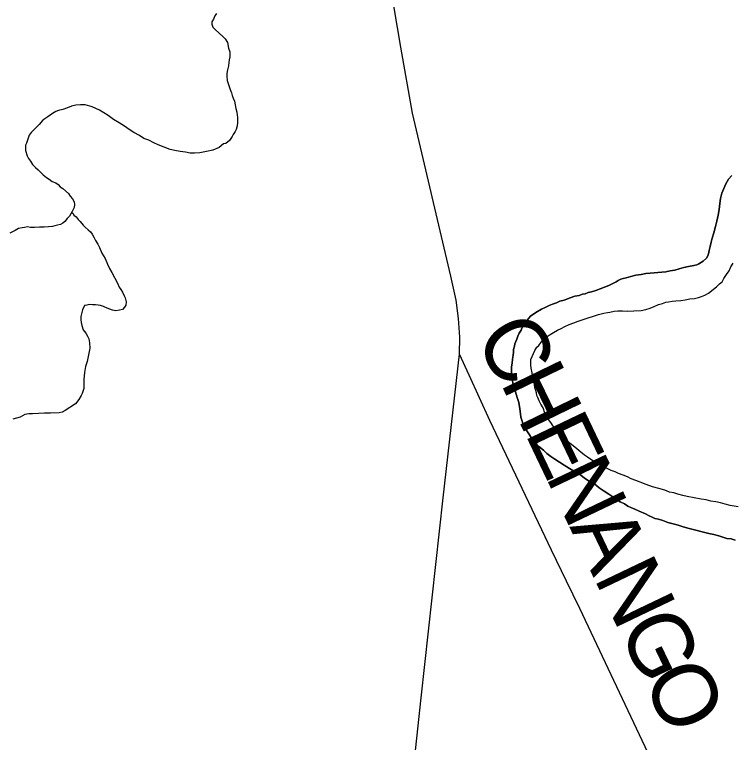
# Model space of a CAD drawing. Extents: x 0 to 34, y 0 to 22.
# Drawn here: x 4.849 to 5.486, y 16.477 to 17.124 of the extents above; entities that cross this region are included whole.
import ezdxf

# ---------------------------------------------------------------- set-up
doc = ezdxf.new("R2010")
doc.units = 0
for name, color, linetype in [('GM_X_Major_River', 7, 'Continuous'), ('GM_X_Minor_River', 7, 'Continuous'), ('GM_X_State_Route', 7, 'Continuous'), ('GM_X_Township_Road', 7, 'Continuous'), ('GM_X_Township_Road_Text', 7, 'Continuous')]:
    doc.layers.add(name, color=color, linetype=linetype)

msp = doc.modelspace()

# ---------------------------------------------------------------- linework, layer by layer
at = {"layer": 'GM_X_Major_River'}
for points in [[(5.48664, 16.98054), (5.48356, 16.97716), (5.48123, 16.973), (5.47928, 16.96884), (5.47771, 16.96468), (5.47652, 16.96013), (5.4757, 16.95558), (5.47526, 16.95027), (5.47444, 16.94533), (5.47323, 16.94003), (5.47203, 16.9351), (5.47044, 16.92941), (5.46887, 16.92487), (5.46806, 16.92108), (5.46726, 16.91729), (5.46646, 16.91388), (5.46566, 16.91084), (5.46526, 16.90895), (5.46409, 16.90706), (5.46102, 16.90444), (5.45719, 16.90182), (5.45528, 16.90109), (5.45261, 16.90036), (5.44804, 16.89965), (5.44384, 16.89856), (5.43965, 16.89747), (5.43583, 16.89637), (5.43164, 16.89566), (5.42783, 16.89495), (5.42441, 16.89461), (5.41375, 16.89359), (5.40995, 16.89326), (5.40576, 16.89255), (5.40119, 16.89184), (5.39661, 16.89076), (5.39242, 16.88967), (5.38975, 16.88894), (5.38784, 16.8882), (5.38554, 16.88709), (5.38363, 16.88597), (5.38057, 16.88448), (5.37713, 16.88262), (5.37331, 16.88115), (5.36949, 16.87967), (5.36567, 16.8782), (5.36186, 16.8771), (5.35881, 16.87638), (5.35613, 16.87527), (5.35385, 16.87492), (5.35079, 16.87381), (5.34698, 16.8731), (5.34279, 16.87163), (5.33744, 16.86979), (5.33363, 16.8687), (5.33057, 16.86721), (5.32713, 16.86611), (5.32408, 16.86501), (5.32102, 16.86352), (5.3172, 16.86167), (5.31222, 16.85869), (5.30761, 16.85532), (5.30453, 16.85194), (5.3026, 16.84892), (5.30028, 16.84628), (5.2991, 16.84287), (5.29755, 16.84023), (5.29638, 16.83759), (5.29521, 16.83494), (5.29364, 16.83078), (5.29323, 16.82888), (5.29244, 16.82585), (5.29241, 16.82357), (5.292, 16.82091), (5.29157, 16.81712), (5.29115, 16.8137), (5.29073, 16.81028), (5.29068, 16.80648), (5.29064, 16.80344), (5.2917, 16.79621), (5.29279, 16.79239), (5.29426, 16.78819), (5.29572, 16.78323), (5.29719, 16.77866), (5.29788, 16.77295), (5.29859, 16.76876), (5.29893, 16.76571), (5.29966, 16.76304), (5.30077, 16.76037), (5.30225, 16.75693), (5.30411, 16.75349), (5.30673, 16.75003)], [(5.30673, 16.75003), (5.30411, 16.75349), (5.30225, 16.75693), (5.30077, 16.76037), (5.29966, 16.76304), (5.29893, 16.76571), (5.29859, 16.76876), (5.29788, 16.77295), (5.29719, 16.77866), (5.29572, 16.78323), (5.29426, 16.78819), (5.29279, 16.79239), (5.2917, 16.79621), (5.29064, 16.80344), (5.29068, 16.80648), (5.29073, 16.81028), (5.29115, 16.8137), (5.29157, 16.81712), (5.292, 16.82091), (5.29241, 16.82357), (5.29244, 16.82585), (5.29323, 16.82888), (5.29364, 16.83078), (5.29521, 16.83494), (5.29638, 16.83759), (5.29755, 16.84023), (5.2991, 16.84287), (5.30028, 16.84628), (5.3026, 16.84892), (5.30453, 16.85194), (5.30761, 16.85532), (5.31222, 16.85869), (5.3172, 16.86167), (5.32102, 16.86352), (5.32408, 16.86501), (5.32713, 16.86611), (5.33057, 16.86721), (5.33363, 16.8687), (5.33744, 16.86979), (5.34279, 16.87163), (5.34698, 16.8731), (5.35079, 16.87381), (5.35385, 16.87492), (5.35613, 16.87527), (5.35881, 16.87638), (5.36186, 16.8771), (5.36567, 16.8782), (5.36949, 16.87967), (5.37331, 16.88115), (5.37713, 16.88262), (5.38057, 16.88448), (5.38363, 16.88597), (5.38554, 16.88709), (5.38784, 16.8882), (5.38975, 16.88894), (5.39242, 16.88967), (5.39661, 16.89076), (5.40119, 16.89184), (5.40576, 16.89255), (5.40995, 16.89326), (5.41375, 16.89359), (5.42441, 16.89461), (5.42783, 16.89495), (5.43164, 16.89566), (5.43583, 16.89637), (5.43965, 16.89747), (5.44384, 16.89856), (5.44804, 16.89965), (5.45261, 16.90036), (5.45528, 16.90109), (5.45719, 16.90182), (5.46102, 16.90444), (5.46409, 16.90706), (5.46526, 16.90895), (5.46566, 16.91084), (5.46646, 16.91388), (5.46726, 16.91729), (5.46806, 16.92108), (5.46887, 16.92487), (5.47044, 16.92941), (5.47203, 16.9351), (5.47323, 16.94003), (5.47444, 16.94533), (5.47526, 16.95027), (5.4757, 16.95558), (5.47652, 16.96013), (5.47771, 16.96468), (5.47928, 16.96884), (5.48123, 16.973), (5.48356, 16.97716), (5.48664, 16.98054)], [(5.4214, 16.86575), (5.42484, 16.86685), (5.42789, 16.86796), (5.43018, 16.86831), (5.4336, 16.86865), (5.43665, 16.86899), (5.44121, 16.86932), (5.44502, 16.87004), (5.44921, 16.87075), (5.4534, 16.87108), (5.45683, 16.87218), (5.4595, 16.87291), (5.46256, 16.87401), (5.46562, 16.87587), (5.47291, 16.88149), (5.4756, 16.88412), (5.4779, 16.88599), (5.47946, 16.88901), (5.48178, 16.89241), (5.48411, 16.8958), (5.48567, 16.8992), (5.48761, 16.9026)], [(5.4214, 16.86575), (5.42484, 16.86685), (5.42789, 16.86796), (5.43018, 16.86831), (5.4336, 16.86865), (5.43665, 16.86899), (5.44121, 16.86932), (5.44502, 16.87004), (5.44921, 16.87075), (5.4534, 16.87108), (5.45683, 16.87218), (5.4595, 16.87291), (5.46256, 16.87401), (5.46562, 16.87587), (5.47291, 16.88149), (5.4756, 16.88412), (5.4779, 16.88599), (5.47946, 16.88901), (5.48178, 16.89241), (5.48411, 16.8958), (5.48567, 16.8992), (5.48761, 16.9026)], [(5.49222, 16.68587), (5.48502, 16.6871), (5.48047, 16.68829), (5.4763, 16.68948), (5.47213, 16.69029), (5.46796, 16.6911), (5.46379, 16.69229), (5.45924, 16.69273), (5.44672, 16.69516), (5.44293, 16.69596), (5.43838, 16.69716), (5.43497, 16.69834), (5.43118, 16.69914), (5.42702, 16.70071), (5.42172, 16.7023), (5.41604, 16.70388), (5.41036, 16.70585), (5.40506, 16.70781), (5.40127, 16.70938), (5.39711, 16.71095), (5.39371, 16.71251), (5.38993, 16.71408), (5.38576, 16.71565), (5.38274, 16.7172), (5.37933, 16.71838), (5.37518, 16.72033), (5.37102, 16.72228), (5.36724, 16.72423), (5.36422, 16.72616), (5.36121, 16.7281), (5.35819, 16.73004), (5.35555, 16.73197), (5.35216, 16.73467), (5.34689, 16.73891), (5.34275, 16.74238), (5.33899, 16.74585), (5.33561, 16.74893), (5.3326, 16.75201), (5.32998, 16.75508), (5.32773, 16.75777), (5.32549, 16.76084), (5.32362, 16.76352), (5.32213, 16.76619), (5.32027, 16.76926), (5.3188, 16.77384), (5.31656, 16.77729), (5.31508, 16.78034), (5.31397, 16.78302), (5.31323, 16.78493), (5.31288, 16.78721), (5.31214, 16.7895), (5.31141, 16.79179), (5.31107, 16.79484), (5.31035, 16.79789), (5.30963, 16.80132), (5.30891, 16.80513), (5.3082, 16.80932), (5.30785, 16.81198), (5.30791, 16.81692), (5.30909, 16.81957), (5.31026, 16.82222), (5.31143, 16.82486), (5.31299, 16.82789), (5.31491, 16.82938), (5.31684, 16.8324), (5.31877, 16.83428), (5.32146, 16.83691), (5.32491, 16.83915), (5.32797, 16.84101), (5.33141, 16.84287), (5.33485, 16.84435), (5.33792, 16.84622), (5.34174, 16.84807), (5.34594, 16.84954), (5.34976, 16.85102), (5.35357, 16.85211), (5.35892, 16.85395), (5.3635, 16.85542), (5.36808, 16.85688), (5.37265, 16.85797), (5.37608, 16.85869), (5.37799, 16.85905), (5.3818, 16.85976), (5.38522, 16.8601), (5.3894, 16.86005), (5.39396, 16.86), (5.39929, 16.86031), (5.40575, 16.86062), (5.40994, 16.86133), (5.41376, 16.86242), (5.41758, 16.8639), (5.4214, 16.86575)], [(5.49222, 16.68587), (5.48502, 16.6871), (5.48047, 16.68829), (5.4763, 16.68948), (5.47213, 16.69029), (5.46796, 16.6911), (5.46379, 16.69229), (5.45924, 16.69273), (5.44672, 16.69516), (5.44293, 16.69596), (5.43838, 16.69716), (5.43497, 16.69834), (5.43118, 16.69914), (5.42702, 16.70071), (5.42172, 16.7023), (5.41604, 16.70388), (5.41036, 16.70585), (5.40506, 16.70781), (5.40127, 16.70938), (5.39711, 16.71095), (5.39371, 16.71251), (5.38993, 16.71408), (5.38576, 16.71565), (5.38274, 16.7172), (5.37933, 16.71838), (5.37518, 16.72033), (5.37102, 16.72228), (5.36724, 16.72423), (5.36422, 16.72616), (5.36121, 16.7281), (5.35819, 16.73004), (5.35555, 16.73197), (5.35216, 16.73467), (5.34689, 16.73891), (5.34275, 16.74238), (5.33899, 16.74585), (5.33561, 16.74893), (5.3326, 16.75201), (5.32998, 16.75508), (5.32773, 16.75777), (5.32549, 16.76084), (5.32362, 16.76352), (5.32213, 16.76619), (5.32027, 16.76926), (5.3188, 16.77384), (5.31656, 16.77729), (5.31508, 16.78034), (5.31397, 16.78302), (5.31323, 16.78493), (5.31288, 16.78721), (5.31214, 16.7895), (5.31141, 16.79179), (5.31107, 16.79484), (5.31035, 16.79789), (5.30963, 16.80132), (5.30891, 16.80513), (5.3082, 16.80932), (5.30785, 16.81198), (5.30791, 16.81692), (5.30909, 16.81957), (5.31026, 16.82222), (5.31143, 16.82486), (5.31299, 16.82789), (5.31491, 16.82938), (5.31684, 16.8324), (5.31877, 16.83428), (5.32146, 16.83691), (5.32491, 16.83915), (5.32797, 16.84101), (5.33141, 16.84287), (5.33485, 16.84435), (5.33792, 16.84622), (5.34174, 16.84807), (5.34594, 16.84954), (5.34976, 16.85102), (5.35357, 16.85211), (5.35892, 16.85395), (5.3635, 16.85542), (5.36808, 16.85688), (5.37265, 16.85797), (5.37608, 16.85869), (5.37799, 16.85905), (5.3818, 16.85976), (5.38522, 16.8601), (5.3894, 16.86005), (5.39396, 16.86), (5.39929, 16.86031), (5.40575, 16.86062), (5.40994, 16.86133), (5.41376, 16.86242), (5.41758, 16.8639), (5.4214, 16.86575)], [(5.30673, 16.75003), (5.30897, 16.7462), (5.31159, 16.74313), (5.31497, 16.73967), (5.31911, 16.7362), (5.32212, 16.73351), (5.3255, 16.7308), (5.32928, 16.72848), (5.33343, 16.72577), (5.33758, 16.72306), (5.3421, 16.71996), (5.34663, 16.71725), (5.35116, 16.71491), (5.35531, 16.71182), (5.35908, 16.70912), (5.36436, 16.70639), (5.3685, 16.70292), (5.37303, 16.69983), (5.37718, 16.69712), (5.38057, 16.6948), (5.38397, 16.69248), (5.38736, 16.69054), (5.39114, 16.68859), (5.39416, 16.68666), (5.3968, 16.68548), (5.40021, 16.68392), (5.40399, 16.68198), (5.40966, 16.67963), (5.41306, 16.67807), (5.41571, 16.6769), (5.41798, 16.67573), (5.42139, 16.67493), (5.42517, 16.67374), (5.42972, 16.67217), (5.43426, 16.67097), (5.43881, 16.66978), (5.44336, 16.66821), (5.44866, 16.66662), (5.46609, 16.66223), (5.47064, 16.66142), (5.47481, 16.66023), (5.4786, 16.65905), (5.482, 16.65786), (5.4858, 16.65744), (5.48959, 16.65625)], [(5.48959, 16.65625), (5.4858, 16.65744), (5.482, 16.65786), (5.4786, 16.65905), (5.47481, 16.66023), (5.47064, 16.66142), (5.46609, 16.66223), (5.44866, 16.66662), (5.44336, 16.66821), (5.43881, 16.66978), (5.43426, 16.67097), (5.42972, 16.67217), (5.42517, 16.67374), (5.42139, 16.67493), (5.41798, 16.67573), (5.41571, 16.6769), (5.41306, 16.67807), (5.40966, 16.67963), (5.40399, 16.68198), (5.40021, 16.68392), (5.3968, 16.68548), (5.39416, 16.68666), (5.39114, 16.68859), (5.38736, 16.69054), (5.38397, 16.69248), (5.38057, 16.6948), (5.37718, 16.69712), (5.37303, 16.69983), (5.3685, 16.70292), (5.36436, 16.70639), (5.35908, 16.70912), (5.35531, 16.71182), (5.35116, 16.71491), (5.34663, 16.71725), (5.3421, 16.71996), (5.33758, 16.72306), (5.33343, 16.72577), (5.32928, 16.72848), (5.3255, 16.7308), (5.32212, 16.73351), (5.31911, 16.7362), (5.31497, 16.73967), (5.31159, 16.74313), (5.30897, 16.7462), (5.30673, 16.75003)]]:
    msp.add_lwpolyline(points, dxfattribs=at)
at = {"layer": 'GM_X_Minor_River'}
for points in [[(5.02841, 17.12434), (5.02687, 17.12246), (5.02569, 17.11943), (5.02414, 17.11717), (5.02411, 17.11489), (5.02522, 17.11221), (5.0271, 17.11029), (5.03424, 17.10375), (5.03612, 17.10182), (5.03798, 17.09876), (5.03907, 17.0938), (5.04016, 17.09037), (5.04014, 17.08847), (5.04011, 17.08581), (5.0397, 17.08315), (5.03929, 17.08088), (5.03887, 17.07784), (5.03807, 17.07443), (5.03765, 17.07101), (5.03762, 17.06835), (5.03796, 17.06493), (5.03906, 17.06149), (5.04052, 17.05691), (5.04163, 17.05386), (5.04236, 17.05157), (5.04309, 17.04928), (5.0442, 17.04661), (5.04492, 17.04318), (5.04564, 17.04013), (5.04636, 17.0367), (5.04671, 17.03441), (5.04707, 17.03213), (5.04704, 17.02985), (5.04701, 17.02719), (5.0466, 17.02453), (5.0458, 17.0215), (5.04502, 17.01961), (5.04308, 17.01697), (5.0423, 17.01508), (5.03998, 17.01169), (5.03653, 17.00906), (5.03462, 17.00871), (5.03078, 17.00533), (5.02505, 17.00312), (5.01933, 17.00167), (5.01362, 17.00059), (5.00867, 17.00027), (5.00487, 17.00032), (5.0007, 17.00113), (4.99614, 17.00194), (4.99121, 17.00276), (4.98704, 17.00357), (4.97645, 17.00788), (4.97267, 17.00944), (4.96813, 17.01178), (4.96359, 17.01335), (4.95982, 17.01606), (4.95491, 17.01878), (4.95076, 17.02149), (4.94661, 17.0242), (4.94171, 17.0273), (4.93681, 17.0304), (4.93191, 17.03387), (4.92436, 17.03853), (4.91793, 17.04164), (4.91149, 17.04324), (4.90731, 17.04329), (4.90313, 17.04296), (4.89932, 17.04224), (4.89588, 17.04076), (4.89168, 17.03929), (4.88786, 17.0382), (4.88557, 17.03746), (4.88251, 17.0356), (4.87829, 17.03261), (4.87407, 17.02962), (4.87061, 17.02586), (4.86676, 17.0221), (4.86368, 17.01872)], [(4.86368, 17.01872), (4.86175, 17.01646), (4.86057, 17.01267), (4.85938, 17.00927), (4.8586, 17.00737), (4.85857, 17.00509), (4.85854, 17.00281), (4.86001, 16.99785), (4.86112, 16.99556), (4.86299, 16.99326), (4.86486, 16.99019), (4.86749, 16.9875), (4.86974, 16.98557), (4.87237, 16.98288), (4.87425, 16.98096), (4.87726, 16.97864), (4.87953, 16.97709), (4.88216, 16.97516), (4.88557, 16.97398), (4.88745, 16.97244), (4.88933, 16.97052), (4.89159, 16.96897), (4.89686, 16.96435), (4.89835, 16.96205), (4.90022, 16.95974), (4.90171, 16.95706), (4.90207, 16.95478), (4.90165, 16.95212), (4.90009, 16.94834), (4.89776, 16.94419), (4.89545, 16.94231), (4.89352, 16.93968), (4.8916, 16.93818), (4.88969, 16.93706), (4.88702, 16.93633), (4.88473, 16.9356), (4.88244, 16.93525), (4.87902, 16.93491), (4.87521, 16.93457), (4.87103, 16.93462), (4.86647, 16.9343), (4.86305, 16.93434), (4.86039, 16.93475), (4.85772, 16.9344), (4.85544, 16.93405), (4.85239, 16.93332), (4.84932, 16.93146), (4.84474, 16.92923)], [(4.89961, 16.94749), (4.90083, 16.94681), (4.90157, 16.94528), (4.90345, 16.94374), (4.90533, 16.94144), (4.9072, 16.93952), (4.90983, 16.93644), (4.9117, 16.93452), (4.91434, 16.93221), (4.91622, 16.93028), (4.91771, 16.92837), (4.9192, 16.92569), (4.92068, 16.92263), (4.92293, 16.91956), (4.92441, 16.9165), (4.92625, 16.91154), (4.92923, 16.90656), (4.93146, 16.90159), (4.93331, 16.89777), (4.93517, 16.89433), (4.94038, 16.88476), (4.94186, 16.88132), (4.94335, 16.87903), (4.94484, 16.87673), (4.94632, 16.87367), (4.94706, 16.87176), (4.94816, 16.86832), (4.94775, 16.86529), (4.94658, 16.8634), (4.94466, 16.86152), (4.94199, 16.8608), (4.93894, 16.86007), (4.93591, 16.86087), (4.93099, 16.86245), (4.92796, 16.864), (4.92531, 16.8648), (4.92304, 16.8652), (4.92076, 16.86561), (4.9181, 16.86564), (4.91506, 16.86568), (4.91315, 16.86532), (4.91087, 16.86497), (4.9093, 16.86118), (4.90771, 16.85512), (4.90767, 16.85208), (4.90803, 16.84979), (4.90875, 16.84712), (4.90985, 16.84331), (4.91209, 16.84024), (4.91358, 16.83756), (4.91469, 16.83527), (4.91541, 16.83184), (4.91573, 16.82689), (4.91452, 16.82121), (4.91331, 16.81514), (4.91173, 16.8106), (4.91091, 16.80528), (4.91046, 16.79921), (4.9104, 16.79465), (4.91036, 16.79123), (4.90957, 16.78857), (4.90879, 16.78668), (4.908, 16.78479), (4.90606, 16.78139), (4.90297, 16.77763), (4.89378, 16.77166), (4.8911, 16.77017), (4.88843, 16.76944), (4.88082, 16.76915), (4.8755, 16.76921), (4.86485, 16.76858), (4.86143, 16.76862), (4.858, 16.7679), (4.85379, 16.76567), (4.84731, 16.76384)]]:
    msp.add_lwpolyline(points, dxfattribs=at)
at = {"layer": 'GM_X_State_Route'}
msp.add_lwpolyline([(5.17842, 16.22124), (5.19289, 16.3535), (5.21044, 16.51624), (5.22974, 16.6939), (5.24444, 16.82177), (5.24466, 16.83668), (5.24356, 16.85335), (5.24137, 16.8698), (5.23676, 16.89107), (5.20254, 17.03583), (5.19224, 17.09461), (5.16306, 17.26613), (5.1464, 17.36833), (5.13389, 17.47471), (5.13104, 17.4984), (5.12578, 17.52647), (5.1135, 17.58328), (5.07796, 17.72968)], dxfattribs=at)
at = {"layer": 'GM_X_Township_Road'}
msp.add_lwpolyline([(5.55831, 16.21486), (5.52701, 16.24918), (5.50022, 16.27703), (5.49494, 16.28313), (5.49232, 16.28884), (5.48895, 16.29721), (5.48559, 16.30975), (5.48336, 16.31812), (5.47586, 16.33524), (5.40941, 16.47265), (5.35124, 16.59558), (5.3396, 16.61994), (5.32609, 16.64735), (5.27129, 16.76267), (5.25291, 16.80301), (5.24444, 16.82177)], dxfattribs=at)

# ---------------------------------------------------------------- texts
at = {"layer": 'GM_X_Township_Road_Text'}
for s, rotation, p in [('C', 301.63512, (5.25648, 16.83517)), ('H', 295.88245, (5.28023, 16.79675)), ('E', 295.53005, (5.30202, 16.75185)), ('N', 295.5191, (5.32033, 16.71351)), ('A', 295.5222, (5.34188, 16.66838)), ('N', 295.52807, (5.36342, 16.62325)), ('G', 295.5191, (5.38497, 16.57814)), ('O', 295.5222, (5.40651, 16.53302))]:
    msp.add_text(s, height=0.05682, rotation=rotation, dxfattribs=at).set_placement(p)

doc.saveas('drawing.dxf')
